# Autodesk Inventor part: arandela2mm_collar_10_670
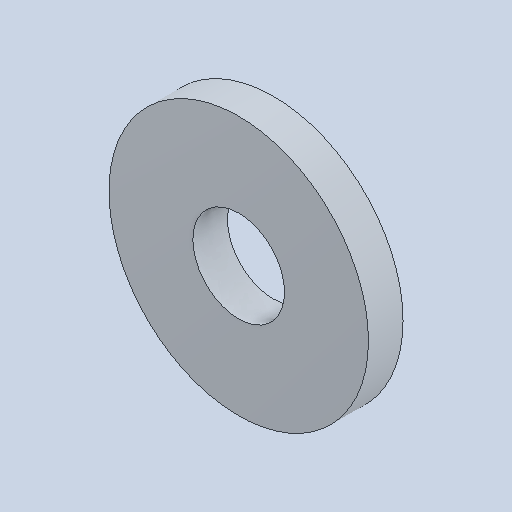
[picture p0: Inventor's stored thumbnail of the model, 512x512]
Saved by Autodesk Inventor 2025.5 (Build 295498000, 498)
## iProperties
Created: 2026-10
Part Number: arandela2mm_collar_10_670
Material: Genérico
Document SubType Name: Modeling
Designer: Luis M
Density: 1 g/cm^3
Appearance: Valor por defecto
Author: Luis M
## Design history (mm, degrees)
feature "Base1"
node "Sólido1"
